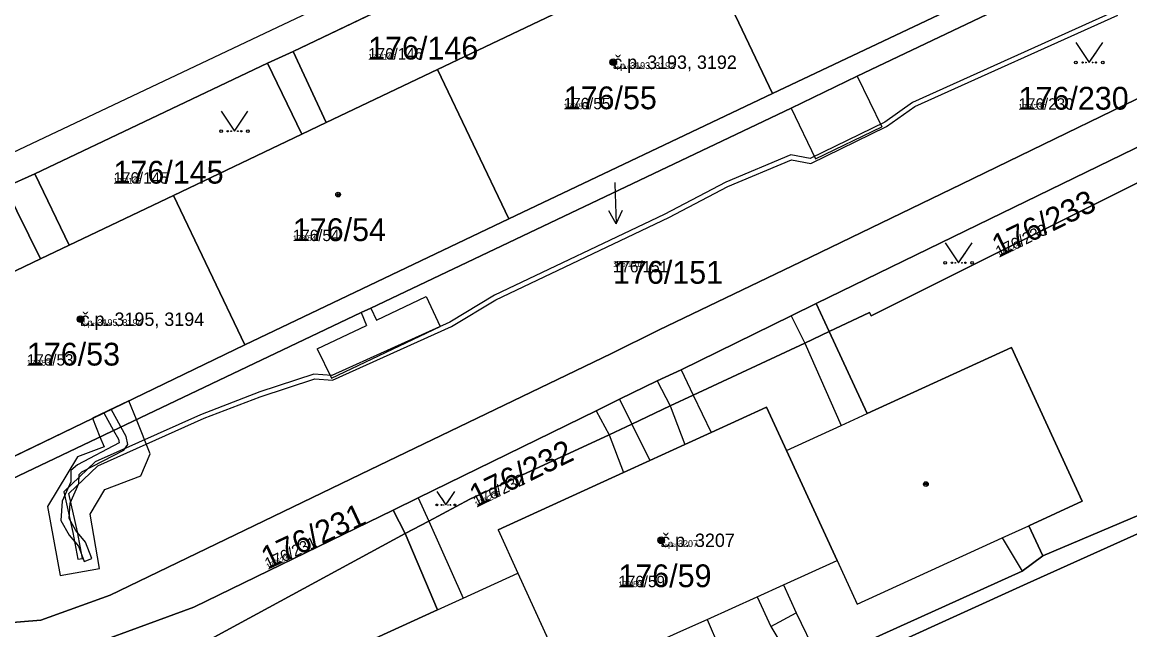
# Model space of a CAD drawing. Extents: x -759873 to -758487, y -975024 to -973516.
# Drawn here: x -759294.8 to -759212.2, y -974781.5 to -974736.1 of the extents above; entities that cross this region are included whole.
import ezdxf

# ---------------------------------------------------------------- set-up
doc = ezdxf.new("R2010")
doc.units = 0
for name, color, linetype in [('KAT_02_hranice parcel', 7, 'Continuous'), ('KAT_03_1000_st čísla parcelní', 7, 'Continuous'), ('KAT_03_1000_čísla parcelní', 7, 'Continuous'), ('KAT_03_1000_čísla popisná', 7, 'Continuous'), ('KAT_03_250_st čísla parcelní', 7, 'Continuous'), ('KAT_03_250_čísla parcelní', 7, 'Continuous'), ('KAT_03_250_čísla popisná', 7, 'Continuous'), ('KAT_03_500_st čísla parcelní', 7, 'Continuous'), ('KAT_03_500_čísla parcelní', 7, 'Continuous'), ('KAT_03_500_čísla popisná', 7, 'Continuous'), ('KAT_04_vnitřní kresba', 7, 'Continuous'), ('KAT_05_1000_značky kultur', 7, 'Continuous'), ('KAT_05_250_značky kultur', 7, 'Continuous'), ('KAT_05_500_značky kultur', 7, 'Continuous'), ('KAT_07_1000_značky budov', 7, 'Continuous'), ('KAT_07_250_značky budov', 7, 'Continuous'), ('KAT_07_500_značky budov', 7, 'Continuous'), ('KAT_10_věcná břemena', 7, 'Continuous'), ('KAT_12_pomocná šipka', 7, 'Continuous'), ('KAT_14_plocha_budovy', 7, 'Continuous'), ('KAT_14_plocha_pozemek', 7, 'Continuous')]:
    doc.layers.add(name, color=color, linetype=linetype)

msp = doc.modelspace()

# ---------------------------------------------------------------- linework, layer by layer
at = {"layer": 'KAT_02_hranice parcel'}
for p, q in [((-759256.62, -974729.68), (-759274.61, -974738.28)), ((-759238.84, -974741.43), (-759244.13, -974730.27)), ((-759238.84, -974741.43), (-759219.12, -974732.06)), ((-759274.61, -974738.28), (-759276.51, -974739.17)), ((-759276.51, -974739.17), (-759293.88, -974747.43)), ((-759258.52, -974750.77), (-759263.84, -974739.63)), ((-759258.52, -974750.77), (-759238.84, -974741.43)), ((-759293.88, -974747.43), (-759296.1, -974748.42)), ((-759278.22, -974760.18), (-759283.54, -974749.04)), ((-759278.22, -974760.18), (-759258.52, -974750.77)), ((-759234.61, -974759.19), (-759235.58, -974757.1)), ((-759297.83, -974769.65), (-759278.22, -974760.18)), ((-759267.15, -974772.52), (-759266.24, -974774.27))]:
    msp.add_line(p, q, dxfattribs=at)
for points in [[(-759297.2, -974770.95), (-759269.53, -974757.78), (-759268.81, -974757.44), (-759237.44, -974742.52), (-759232.51, -974740.14), (-759189.23, -974719.52), (-759188.5, -974719.17), (-759159.12, -974705.45)], [(-759301.24, -974780.99), (-759301.03, -974781.35), (-759293.44, -974780.74), (-759288.26, -974778.87), (-759268.89, -974769.51), (-759250.85, -974760.82), (-759247.34, -974759.1), (-759236.73, -974753.99), (-759224.73, -974748.18), (-759206.51, -974739.34), (-759188.27, -974730.61), (-759177.27, -974725.26), (-759160.55, -974717.22), (-759156.31, -974714.42), (-759154.33, -974710.16)], [(-759256.62, -974729.68), (-759255.6, -974731.84), (-759256.12, -974732.12), (-759254.73, -974735.3), (-759263.84, -974739.63)], [(-759235.58, -974757.1), (-759223.52, -974751.22), (-759205.57, -974742.5), (-759186.91, -974733.43), (-759186.53, -974735.82)], [(-759234.61, -974759.19), (-759231.61, -974757.76), (-759231.48, -974758.03), (-759210.11, -974747.34), (-759186.53, -974735.82)], [(-759183.19, -974736.35), (-759176.58, -974737.4), (-759182.07, -974749.11), (-759190.12, -974766.32), (-759202.77, -974781.98), (-759209.13, -974788.81), (-759225.44, -974805.2), (-759239.06, -974815.12), (-759245.96, -974818.65), (-759258.28, -974823.9), (-759278.94, -974832.86), (-759280.49, -974821.62), (-759282.67, -974805.49), (-759285.3, -974797.52), (-759288.93, -974786.59), (-759266.24, -974774.27)], [(-759263.84, -974739.63), (-759272.15, -974743.6), (-759274.61, -974738.28)], [(-759276.51, -974739.17), (-759273.96, -974744.46), (-759283.54, -974749.04)], [(-759283.54, -974749.04), (-759291.32, -974752.75), (-759293.88, -974747.43)], [(-759296.1, -974748.42), (-759293.45, -974753.77), (-759303.23, -974758.44)], [(-759267.15, -974772.52), (-759265.27, -974771.61), (-759252, -974765.12), (-759250.25, -974764.25), (-759247.44, -974762.88), (-759245.65, -974762.05), (-759237.44, -974758.02), (-759235.58, -974757.1)], [(-759234.61, -974759.19), (-759236.42, -974760.06), (-759244.75, -974763.94), (-759246.47, -974764.74), (-759249.33, -974766.1), (-759251.03, -974766.91), (-759261.42, -974771.71), (-759264.49, -974773.34), (-759266.24, -974774.27)], [(-759218.68, -974775.94), (-759219.72, -974773.68), (-759215.74, -974771.85), (-759221, -974760.37), (-759231.77, -974765.31), (-759234.61, -974759.19)], [(-759264.25, -974796.7), (-759273.82, -974801.42), (-759273.86, -974802.58), (-759263.4, -974797.86), (-759250.81, -974792.11), (-759234.75, -974784.78), (-759219.84, -974778), (-759205.42, -974771.5), (-759205, -974770.14), (-759218.68, -974775.94)], [(-759293.14, -974783.84), (-759282.01, -974779.76), (-759267.15, -974772.52)], [(-759266.24, -974774.27), (-759263.84, -974779.97), (-759274.56, -974784.87), (-759269.17, -974796.23), (-759265.28, -974794.44), (-759264.25, -974796.7)], [(-759264.25, -974796.7), (-759262.28, -974795.8), (-759251.19, -974791.13), (-759249.43, -974790.33), (-759242.7, -974787.21), (-759241.08, -974786.49), (-759236.91, -974784.6), (-759235.27, -974783.88), (-759220.2, -974777.07), (-759218.68, -974775.94)]]:
    msp.add_lwpolyline(points, dxfattribs=at)
at = {"layer": 'KAT_03_1000_čísla popisná'}
for centre in [(-759250.72, -974739.09), (-759290.46, -974758.27), (-759247.15, -974774.77)]:
    msp.add_circle(centre, 0.25, dxfattribs=at)
at = {"layer": 'KAT_03_250_čísla popisná'}
for centre in [(-759250.72, -974739.09), (-759290.46, -974758.27), (-759247.15, -974774.77)]:
    msp.add_circle(centre, 0.0625, dxfattribs=at)
at = {"layer": 'KAT_03_500_čísla popisná'}
for centre in [(-759250.72, -974739.09), (-759290.46, -974758.27), (-759247.15, -974774.77)]:
    msp.add_circle(centre, 0.125, dxfattribs=at)
at = {"layer": 'KAT_04_vnitřní kresba'}
for p, q in [((-759296.46, -974746.27), (-759255.11, -974726.67)), ((-759232.51, -974740.14), (-759230.68, -974743.92)), ((-759237.44, -974742.52), (-759235.62, -974746.29)), ((-759273.96, -974744.46), (-759272.15, -974743.6)), ((-759235.62, -974746.29), (-759230.68, -974743.92)), ((-759293.45, -974753.77), (-759291.32, -974752.75)), ((-759268.38, -974758.34), (-759264.69, -974756.57)), ((-759264.69, -974756.57), (-759263.64, -974758.81)), ((-759269.53, -974757.78), (-759269.13, -974758.73)), ((-759268.81, -974757.44), (-759268.38, -974758.34)), ((-759237.44, -974758.02), (-759236.42, -974760.06)), ((-759272.8, -974760.48), (-759269.13, -974758.73)), ((-759271.75, -974762.67), (-759263.64, -974758.81)), ((-759272.8, -974760.48), (-759271.75, -974762.67)), ((-759236.42, -974760.06), (-759233.72, -974766.2)), ((-759245.65, -974762.05), (-759244.75, -974763.94)), ((-759247.44, -974762.88), (-759246.47, -974764.74)), ((-759244.75, -974763.94), (-759243.41, -974766.72)), ((-759250.25, -974764.25), (-759249.33, -974766.1)), ((-759246.47, -974764.74), (-759245.39, -974767.62)), ((-759243.41, -974766.72), (-759239.28, -974764.83)), ((-759239.28, -974764.83), (-759237.79, -974768.07)), ((-759252, -974765.12), (-759251.03, -974766.91)), ((-759233.72, -974766.2), (-759231.77, -974765.31)), ((-759249.33, -974766.1), (-759247.98, -974768.81)), ((-759237.79, -974768.07), (-759233.72, -974766.2)), ((-759251.03, -974766.91), (-759249.96, -974769.71)), ((-759245.39, -974767.62), (-759243.41, -974766.72)), ((-759247.98, -974768.81), (-759245.39, -974767.62)), ((-759237.79, -974768.07), (-759234.02, -974776.29)), ((-759249.96, -974769.71), (-759247.98, -974768.81)), ((-759259.31, -974773.99), (-759249.96, -974769.71)), ((-759265.27, -974771.61), (-759264.49, -974773.34)), ((-759264.49, -974773.34), (-759261.92, -974779.09)), ((-759221.71, -974774.59), (-759219.72, -974773.68)), ((-759259.31, -974773.99), (-759257.83, -974777.22)), ((-759232.53, -974779.55), (-759221.71, -974774.59)), ((-759221.71, -974774.59), (-759220.2, -974777.07)), ((-759238.01, -974778.09), (-759234.02, -974776.29)), ((-759234.02, -974776.29), (-759232.53, -974779.55)), ((-759261.92, -974779.09), (-759257.83, -974777.22)), ((-759257.83, -974777.22), (-759254.1, -974785.38)), ((-759239.97, -974778.98), (-759238.01, -974778.09)), ((-759238.01, -974778.09), (-759237.07, -974780.19)), ((-759263.84, -974779.97), (-759261.92, -974779.09)), ((-759243.72, -974780.68), (-759239.97, -974778.98)), ((-759239.97, -974778.98), (-759238.96, -974781.21)), ((-759238.96, -974781.21), (-759237.07, -974780.19)), ((-759237.07, -974780.19), (-759235.27, -974783.88)), ((-759245.67, -974781.56), (-759243.72, -974780.68)), ((-759243.72, -974780.68), (-759242.8, -974782.82)), ((-759238.96, -974781.21), (-759236.91, -974784.6))]:
    msp.add_line(p, q, dxfattribs=at)
at = {"layer": 'KAT_05_1000_značky kultur'}
for points in [[(-759216.2, -974737.609), (-759215.2, -974739.11), (-759214.2, -974737.609)], [(-759279.98, -974742.739), (-759278.98, -974744.24), (-759277.98, -974742.739)], [(-759225.95, -974752.559), (-759224.95, -974754.06), (-759223.95, -974752.559)], [(-759263.88, -974771.124), (-759263.21, -974772.13), (-759262.54, -974771.124)]]:
    msp.add_lwpolyline(points, dxfattribs=at)
for centre, radius in [((-759216.2, -974739.109), 0.1), ((-759214.2, -974739.109), 0.1), ((-759279.98, -974744.239), 0.1), ((-759277.98, -974744.239), 0.1), ((-759225.95, -974754.059), 0.1), ((-759223.95, -974754.059), 0.1), ((-759263.88, -974772.13), 0.067), ((-759262.54, -974772.13), 0.067)]:
    msp.add_circle(centre, radius, dxfattribs=at)
at = {"layer": 'KAT_05_250_značky kultur'}
for points in [[(-759215.45, -974738.735), (-759215.2, -974739.11), (-759214.95, -974738.735)], [(-759279.23, -974743.865), (-759278.98, -974744.24), (-759278.73, -974743.865)], [(-759225.2, -974753.685), (-759224.95, -974754.06), (-759224.7, -974753.685)], [(-759263.378, -974771.878), (-759263.21, -974772.13), (-759263.042, -974771.878)]]:
    msp.add_lwpolyline(points, dxfattribs=at)
for centre, radius in [((-759215.45, -974739.11), 0.025), ((-759214.95, -974739.11), 0.025), ((-759279.23, -974744.24), 0.025), ((-759278.73, -974744.24), 0.025), ((-759225.2, -974754.06), 0.025), ((-759224.7, -974754.06), 0.025), ((-759263.378, -974772.13), 0.0168), ((-759263.042, -974772.13), 0.0168)]:
    msp.add_circle(centre, radius, dxfattribs=at)
at = {"layer": 'KAT_05_500_značky kultur'}
for points in [[(-759215.7, -974738.36), (-759215.2, -974739.11), (-759214.7, -974738.36)], [(-759279.48, -974743.49), (-759278.98, -974744.24), (-759278.48, -974743.49)], [(-759225.45, -974753.309), (-759224.95, -974754.06), (-759224.45, -974753.309)], [(-759263.545, -974771.627), (-759263.21, -974772.13), (-759262.875, -974771.627)]]:
    msp.add_lwpolyline(points, dxfattribs=at)
for centre, radius in [((-759215.7, -974739.11), 0.05), ((-759214.7, -974739.11), 0.05), ((-759279.48, -974744.24), 0.05), ((-759278.48, -974744.24), 0.05), ((-759225.45, -974754.06), 0.05), ((-759224.45, -974754.06), 0.05), ((-759263.545, -974772.13), 0.0335), ((-759262.875, -974772.13), 0.0335)]:
    msp.add_circle(centre, radius, dxfattribs=at)
at = {"layer": 'KAT_07_1000_značky budov'}
for centre in [(-759250.727, -974739.089), (-759271.247, -974748.969), (-759290.467, -974758.269), (-759227.397, -974770.579), (-759247.157, -974774.769)]:
    msp.add_circle(centre, 0.175, dxfattribs=at)
at = {"layer": 'KAT_07_250_značky budov'}
for centre in [(-759250.722, -974739.09), (-759271.242, -974748.97), (-759290.462, -974758.27), (-759227.392, -974770.58), (-759247.152, -974774.77)]:
    msp.add_circle(centre, 0.0437, dxfattribs=at)
at = {"layer": 'KAT_07_500_značky budov'}
for centre in [(-759250.723, -974739.09), (-759271.243, -974748.97), (-759290.463, -974758.27), (-759227.393, -974770.58), (-759247.153, -974774.77)]:
    msp.add_circle(centre, 0.0875, dxfattribs=at)
at = {"layer": 'KAT_10_věcná břemena'}
msp.add_lwpolyline([(-759213.23, -974735.25), (-759228.39, -974742.1), (-759230.46, -974743.57), (-759236.04, -974746.28), (-759237.47, -974746.01), (-759242.32, -974748.05), (-759246.93, -974750.45), (-759259.58, -974756.47), (-759262.92, -974758.48), (-759271.72, -974762.47), (-759273.05, -974762.37), (-759277.1, -974763.7), (-759281.52, -974765.4), (-759289.38, -974768.91), (-759291.71, -974771.15), (-759291.03, -974774.2), (-759290.67, -974776.18), (-759290.33, -974776.12), (-759290.69, -974774.14), (-759291.33, -974771.27), (-759289.18, -974769.21), (-759281.24, -974765.66), (-759277.06, -974764.06), (-759272.99, -974762.71), (-759271.66, -974762.83), (-759262.8, -974758.81), (-759259.48, -974756.83), (-759246.57, -974750.67), (-759242.16, -974748.37), (-759237.43, -974746.37), (-759235.98, -974746.64), (-759230.32, -974743.89), (-759228.21, -974742.4), (-759213.08, -974735.57)], dxfattribs=at)
for points in [[(-759289.02, -974767.05), (-759288.71, -974767.8), (-759290.7, -974768.55), (-759292.92, -974772.24), (-759291.99, -974777.41), (-759289.04, -974776.88), (-759289.76, -974772.82), (-759288.66, -974770.99), (-759285.98, -974769.97), (-759285.26, -974768.33), (-759286.3, -974765.76), (-759286.87, -974764.36), (-759289.58, -974765.66)], [(-759288.19, -974764.99), (-759288.73, -974765.26), (-759288, -974766.57), (-759287.63, -974767.23), (-759287.58, -974767.49), (-759290.7, -974769.15), (-759291.18, -974769.57), (-759291.19, -974770.4), (-759291.83, -974771.86), (-759291.93, -974773.29), (-759291.31, -974774.39), (-759290.62, -974775.22), (-759290.19, -974776.36), (-759289.63, -974776.14), (-759290.1, -974774.92), (-759290.81, -974774.05), (-759291.31, -974773.15), (-759291.23, -974772), (-759290.59, -974770.52), (-759290.58, -974769.85), (-759290.36, -974769.65), (-759287.23, -974768.05), (-759286.94, -974767.61), (-759287.05, -974767.03), (-759287.45, -974766.31)]]:
    msp.add_lwpolyline(points, close=True, dxfattribs=at)
at = {"layer": 'KAT_12_pomocná šipka'}
for p, q in [((-759250.61, -974748.06), (-759250.61, -974748.16)), ((-759250.61, -974748.16), (-759250.505, -974751.159)), ((-759250.505, -974751.159), (-759251.041, -974750.176)), ((-759250.505, -974751.159), (-759250.04, -974750.141))]:
    msp.add_line(p, q, dxfattribs=at)
at = {"layer": 'KAT_14_plocha_budovy'}
for points in [[(-759224.42, -974720.91), (-759232.75, -974724.87), (-759234.55, -974725.72), (-759244.13, -974730.27), (-759252.27, -974734.14), (-759254.73, -974735.3), (-759263.84, -974739.63), (-759258.52, -974750.77), (-759238.84, -974741.43), (-759219.12, -974732.06)], [(-759303.23, -974758.44), (-759297.83, -974769.65), (-759278.22, -974760.18), (-759258.52, -974750.77), (-759263.84, -974739.63), (-759272.15, -974743.6), (-759273.96, -974744.46), (-759283.54, -974749.04), (-759291.32, -974752.75), (-759293.45, -974753.77)], [(-759247.98, -974768.81), (-759249.96, -974769.71), (-759259.31, -974773.99), (-759257.83, -974777.22), (-759254.1, -974785.38), (-759252.19, -974784.51), (-759245.67, -974781.56), (-759243.72, -974780.68), (-759239.97, -974778.98), (-759238.01, -974778.09), (-759234.02, -974776.29), (-759237.79, -974768.07), (-759239.28, -974764.83), (-759243.41, -974766.72), (-759245.39, -974767.62)]]:
    msp.add_lwpolyline(points, close=True, dxfattribs=at)
at = {"layer": 'KAT_14_plocha_pozemek'}
for points in [[(-759296.1, -974748.42), (-759293.88, -974747.43), (-759276.51, -974739.17), (-759274.61, -974738.28), (-759256.62, -974729.68), (-759254.74, -974728.81), (-759237.16, -974720.36), (-759235.3, -974719.48), (-759217.19, -974710.86), (-759215.37, -974709.97), (-759197.64, -974701.59), (-759195.81, -974700.76), (-759189.73, -974699.13), (-759180.57, -974698.08), (-759170.07, -974699.86), (-759160.58, -974704.45)], [(-759159.12, -974705.45), (-759188.5, -974719.17), (-759189.23, -974719.52), (-759232.51, -974740.14), (-759237.44, -974742.52), (-759268.81, -974757.44), (-759269.53, -974757.78), (-759297.2, -974770.95), (-759305.42, -974769.66), (-759305.13, -974770.39), (-759301.24, -974780.99), (-759301.03, -974781.35), (-759293.44, -974780.74), (-759288.26, -974778.87), (-759268.89, -974769.51), (-759250.85, -974760.82), (-759247.34, -974759.1), (-759236.73, -974753.99), (-759224.73, -974748.18), (-759206.51, -974739.34), (-759188.27, -974730.61), (-759177.27, -974725.26), (-759160.55, -974717.22)], [(-759160.55, -974717.22), (-759177.27, -974725.26), (-759188.27, -974730.61), (-759206.51, -974739.34), (-759224.73, -974748.18), (-759236.73, -974753.99), (-759247.34, -974759.1), (-759250.85, -974760.82), (-759268.89, -974769.51), (-759288.26, -974778.87), (-759293.44, -974780.74), (-759301.03, -974781.35)], [(-759293.14, -974783.84), (-759282.01, -974779.76), (-759267.15, -974772.52), (-759265.27, -974771.61), (-759252, -974765.12), (-759250.25, -974764.25), (-759247.44, -974762.88), (-759245.65, -974762.05), (-759237.44, -974758.02), (-759235.58, -974757.1), (-759223.52, -974751.22), (-759205.57, -974742.5), (-759186.91, -974733.43), (-759186.53, -974735.82), (-759183.19, -974736.35), (-759180.19, -974732.09), (-759175.88, -974728.64), (-759167.17, -974727.13), (-759165.81, -974724.55), (-759163.54, -974722.39)], [(-759202.77, -974781.98), (-759190.12, -974766.32), (-759182.07, -974749.11), (-759176.58, -974737.4), (-759183.19, -974736.35), (-759186.53, -974735.82), (-759210.11, -974747.34), (-759231.48, -974758.03), (-759231.61, -974757.76), (-759234.61, -974759.19), (-759231.77, -974765.31), (-759221, -974760.37), (-759215.74, -974771.85), (-759219.72, -974773.68), (-759218.68, -974775.94), (-759205, -974770.14), (-759205.42, -974771.5), (-759219.84, -974778), (-759234.75, -974784.78)], [(-759235.27, -974783.88), (-759220.2, -974777.07), (-759218.68, -974775.94), (-759219.72, -974773.68), (-759215.74, -974771.85), (-759221, -974760.37), (-759231.77, -974765.31), (-759234.61, -974759.19), (-759236.42, -974760.06), (-759244.75, -974763.94), (-759246.47, -974764.74), (-759249.33, -974766.1), (-759251.03, -974766.91), (-759261.42, -974771.71), (-759264.49, -974773.34), (-759266.24, -974774.27), (-759263.84, -974779.97), (-759274.56, -974784.87)], [(-759288.93, -974786.59), (-759266.24, -974774.27), (-759267.15, -974772.52), (-759282.01, -974779.76), (-759293.14, -974783.84)], [(-759274.56, -974784.87), (-759263.84, -974779.97), (-759266.24, -974774.27), (-759288.93, -974786.59)]]:
    msp.add_lwpolyline(points, dxfattribs=at)
for points in [[(-759189.23, -974719.52), (-759188.5, -974719.17), (-759159.12, -974705.45), (-759160.58, -974704.45), (-759179.67, -974713.25), (-759199.38, -974722.66), (-759219.12, -974732.06), (-759238.84, -974741.43), (-759258.52, -974750.77), (-759278.22, -974760.18), (-759297.83, -974769.65), (-759297.2, -974770.95), (-759269.53, -974757.78), (-759268.81, -974757.44), (-759237.44, -974742.52), (-759232.51, -974740.14)], [(-759234.55, -974725.72), (-759244.13, -974730.27), (-759238.84, -974741.43), (-759219.12, -974732.06), (-759224.42, -974720.91), (-759232.75, -974724.87), (-759235.3, -974719.48), (-759237.16, -974720.36)], [(-759254.73, -974735.3), (-759263.84, -974739.63), (-759258.52, -974750.77), (-759238.84, -974741.43), (-759244.13, -974730.27), (-759252.27, -974734.14), (-759254.74, -974728.81), (-759256.62, -974729.68), (-759255.6, -974731.84), (-759256.12, -974732.12)], [(-759256.62, -974729.68), (-759274.61, -974738.28), (-759272.15, -974743.6), (-759263.84, -974739.63), (-759254.73, -974735.3), (-759256.12, -974732.12), (-759255.6, -974731.84)], [(-759231.61, -974757.76), (-759231.48, -974758.03), (-759210.11, -974747.34), (-759186.53, -974735.82), (-759186.91, -974733.43), (-759205.57, -974742.5), (-759223.52, -974751.22), (-759235.58, -974757.1), (-759234.61, -974759.19)], [(-759258.52, -974750.77), (-759263.84, -974739.63), (-759272.15, -974743.6), (-759274.61, -974738.28), (-759276.51, -974739.17), (-759273.96, -974744.46), (-759283.54, -974749.04), (-759278.22, -974760.18)], [(-759276.51, -974739.17), (-759293.88, -974747.43), (-759291.32, -974752.75), (-759283.54, -974749.04), (-759273.96, -974744.46)], [(-759293.88, -974747.43), (-759296.1, -974748.42), (-759293.45, -974753.77), (-759303.23, -974758.44), (-759297.83, -974769.65), (-759278.22, -974760.18), (-759283.54, -974749.04), (-759291.32, -974752.75)], [(-759296.1, -974748.42), (-759305.91, -974753.05), (-759303.23, -974758.44), (-759293.45, -974753.77)], [(-759234.61, -974759.19), (-759235.58, -974757.1), (-759237.44, -974758.02), (-759245.65, -974762.05), (-759247.44, -974762.88), (-759250.25, -974764.25), (-759252, -974765.12), (-759265.27, -974771.61), (-759267.15, -974772.52), (-759266.24, -974774.27), (-759264.49, -974773.34), (-759261.42, -974771.71), (-759251.03, -974766.91), (-759249.33, -974766.1), (-759246.47, -974764.74), (-759244.75, -974763.94), (-759236.42, -974760.06)], [(-759205, -974770.14), (-759218.68, -974775.94), (-759220.2, -974777.07), (-759235.27, -974783.88), (-759236.91, -974784.6), (-759241.08, -974786.49), (-759242.7, -974787.21), (-759249.43, -974790.33), (-759251.19, -974791.13), (-759262.28, -974795.8), (-759264.25, -974796.7), (-759273.82, -974801.42), (-759273.86, -974802.58), (-759263.4, -974797.86), (-759250.81, -974792.11), (-759234.75, -974784.78), (-759219.84, -974778), (-759205.42, -974771.5)]]:
    msp.add_lwpolyline(points, close=True, dxfattribs=at)

# ---------------------------------------------------------------- texts
at = {"layer": 'KAT_03_1000_st čísla parcelní'}
for s, p in [('176/55', (-759254.42, -974742.6)), ('176/54', (-759274.63, -974752.44)), ('176/53', (-759294.47, -974761.73)), ('176/59', (-759250.34, -974778.27))]:
    msp.add_text(s, height=1.7, dxfattribs=at).set_placement(p)
at = {"layer": 'KAT_03_1000_čísla parcelní'}
for s, p in [('176/146', (-759269.01, -974738.89)), ('176/230', (-759220.48, -974742.63)), ('176/145', (-759288.01, -974748.15)), ('176/151', (-759250.74, -974755.623))]:
    msp.add_text(s, height=1.7, dxfattribs=at).set_placement(p)
for s, rotation, p in [('176/233', 26, (-759221.937, -974753.683)), ('176/232', 26, (-759260.917, -974772.333)), ('176/231', 25, (-759276.48, -974776.96))]:
    msp.add_text(s, height=1.7, rotation=rotation, dxfattribs=at).set_placement(p)
at = {"layer": 'KAT_03_1000_čísla popisná'}
for s, p in [('č.p. 3193, 3192', (-759250.72, -974739.59)), ('č.p. 3195, 3194', (-759290.46, -974758.77)), ('č.p. 3207', (-759247.15, -974775.27))]:
    msp.add_text(s, height=1, dxfattribs=at).set_placement(p)
at = {"layer": 'KAT_03_250_st čísla parcelní'}
for s, p in [('176/55', (-759254.42, -974742.6)), ('176/54', (-759274.63, -974752.44)), ('176/53', (-759294.47, -974761.73)), ('176/59', (-759250.34, -974778.27))]:
    msp.add_text(s, height=0.425, dxfattribs=at).set_placement(p)
at = {"layer": 'KAT_03_250_čísla parcelní'}
for s, p in [('176/146', (-759269.01, -974738.89)), ('176/230', (-759220.48, -974742.63)), ('176/145', (-759288.01, -974748.15)), ('176/151', (-759250.74, -974754.348))]:
    msp.add_text(s, height=0.425, dxfattribs=at).set_placement(p)
for s, rotation, p in [('176/233', 26, (-759221.937, -974753.683)), ('176/232', 26, (-759260.917, -974772.333)), ('176/231', 25, (-759276.48, -974776.96))]:
    msp.add_text(s, height=0.425, rotation=rotation, dxfattribs=at).set_placement(p)
at = {"layer": 'KAT_03_250_čísla popisná'}
for s, p in [('č.p. 3193, 3192', (-759250.72, -974739.59)), ('č.p. 3195, 3194', (-759290.46, -974758.77)), ('č.p. 3207', (-759247.15, -974775.27))]:
    msp.add_text(s, height=0.25, dxfattribs=at).set_placement(p)
at = {"layer": 'KAT_03_500_st čísla parcelní'}
for s, p in [('176/55', (-759254.42, -974742.6)), ('176/54', (-759274.63, -974752.44)), ('176/53', (-759294.47, -974761.73)), ('176/59', (-759250.34, -974778.27))]:
    msp.add_text(s, height=0.85, dxfattribs=at).set_placement(p)
at = {"layer": 'KAT_03_500_čísla parcelní'}
for s, p in [('176/146', (-759269.01, -974738.89)), ('176/230', (-759220.48, -974742.63)), ('176/145', (-759288.01, -974748.15)), ('176/151', (-759250.74, -974754.773))]:
    msp.add_text(s, height=0.85, dxfattribs=at).set_placement(p)
for s, rotation, p in [('176/233', 26, (-759221.937, -974753.683)), ('176/232', 26, (-759260.917, -974772.333)), ('176/231', 25, (-759276.48, -974776.96))]:
    msp.add_text(s, height=0.85, rotation=rotation, dxfattribs=at).set_placement(p)
at = {"layer": 'KAT_03_500_čísla popisná'}
for s, p in [('č.p. 3193, 3192', (-759250.72, -974739.59)), ('č.p. 3195, 3194', (-759290.46, -974758.77)), ('č.p. 3207', (-759247.15, -974775.27))]:
    msp.add_text(s, height=0.5, dxfattribs=at).set_placement(p)

doc.saveas('drawing.dxf')
